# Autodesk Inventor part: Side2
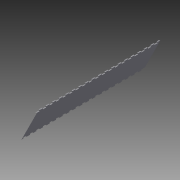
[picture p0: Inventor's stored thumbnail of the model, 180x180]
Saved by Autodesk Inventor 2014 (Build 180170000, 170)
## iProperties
Created: 2014-06
Part Number: Side2
Material: Generic
Document SubType Name: Modeling
Designer: Aser
Density: 1 g/cm^3
Appearance: Default
Author: Aser
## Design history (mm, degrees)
sketch "Sketch1"
  geometry: L1 (-245, -25)-(245, -25); L2 (245, -25)-(245, 25); L3 (245, 25)-(-245, 25); L4 (-245, 25)-(-245, -25); L5 (-245, -25)-(245, 25); L6 (245, -25)-(-245, 25); 1 further point
  constraints: 12 end point, 2 midpoint, 2 parallel, 1 horizontal, 1 perpendicular
  dimensions: "d0" = 490 distance of L2.end L3.end; "d1" = 50 distance of L1.end L2.end
extrude "Extrusion1" new body sketch "Sketch1" distance "d2" = 3; taper "d3" = 0 deg
sketch "Sketch2"
  geometry: L1 (25, 245)-(-25, 245) reference; L2 (-25, -245)-(25, -245) reference; L3 (-22, 242)-(-22, 232) reference; L4 (-22, 232)-(-25, 232) reference; L5 (-25, 242)-(-25, 232) reference; L6 (-22, 242)-(-25, 242) reference; L7 (-22, 222.25)-(-22, 212.25) reference; L8 (-22, 212.25)-(-25, 212.25) reference; L9 (-25, 222.25)-(-25, 212.25) reference; L10 (-22, 222.25)-(-25, 222.25) reference; L11 (-22, 202.5)-(-22, 192.5) reference; L12 (-22, 192.5)-(-25, 192.5) reference; L13 (-25, 202.5)-(-25, 192.5) reference; L14 (-22, 202.5)-(-25, 202.5) reference; L15 (-22, 172.75)-(-22, 182.75) reference; L16 (-22, 172.75)-(-25, 172.75) reference; L17 (-25, 182.75)-(-25, 172.75) reference; L18 (-22, 182.75)-(-25, 182.75) reference; L19 (-22, 163)-(-22, 153) reference; L20 (-22, 153)-(-25, 153) reference; L21 (-25, 163)-(-25, 153) reference; L22 (-22, 163)-(-25, 163) reference; L23 (-22, 133.25)-(-22, 143.25) reference; L24 (-22, 133.25)-(-25, 133.25) reference; L25 (-25, 143.25)-(-25, 133.25) reference; L26 (-22, 143.25)-(-25, 143.25) reference; L27 (-22, 113.5)-(-22, 123.5) reference; L28 (-22, 113.5)-(-25, 113.5) reference; L29 (-25, 123.5)-(-25, 113.5) reference; L30 (-22, 123.5)-(-25, 123.5) reference; L31 (-22, 93.75)-(-22, 103.75) reference; L32 (-22, 93.75)-(-25, 93.75) reference; L33 (-25, 103.75)-(-25, 93.75) reference; L34 (-22, 103.75)-(-25, 103.75) reference; L35 (-22, 84)-(-22, 74) reference; L36 (-22, 74)-(-25, 74) reference; L37 (-25, 84)-(-25, 74) reference; L38 (-22, 84)-(-25, 84) reference; L39 (-22, 64.25)-(-22, 54.25) reference; L40 (-22, 54.25)-(-25, 54.25) reference; L41 (-25, 64.25)-(-25, 54.25) reference; L42 (-22, 64.25)-(-25, 64.25) reference; L43 (-22, 44.5)-(-22, 34.5) reference; L44 (-22, 34.5)-(-25, 34.5) reference; L45 (-25, 44.5)-(-25, 34.5) reference; L46 (-22, 44.5)-(-25, 44.5) reference; L47 (-22, 24.75)-(-22, 14.75) reference; L48 (-22, 14.75)-(-25, 14.75) reference; L49 (-25, 24.75)-(-25, 14.75) reference; L50 (-22, 24.75)-(-25, 24.75) reference; L51 (-22, 5)-(-22, -5) reference; L52 (-22, -5)-(-25, -5) reference; L53 (-25, 5)-(-25, -5) reference; L54 (-22, 5)-(-25, 5) reference; L55 (-22, -14.75)-(-22, -24.75) reference; L56 (-22, -24.75)-(-25, -24.75) reference; L57 (-25, -14.75)-(-25, -24.75) reference; L58 (-22, -14.75)-(-25, -14.75) reference; L59 (-22, -34.5)-(-22, -44.5) reference; L60 (-22, -44.5)-(-25, -44.5) reference; L61 (-25, -34.5)-(-25, -44.5) reference; L62 (-22, -34.5)-(-25, -34.5) reference; L63 (-22, -54.25)-(-22, -64.25) reference; L64 (-22, -64.25)-(-25, -64.25) reference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; 1 further point
  constraints: 100 symmetric about line, 2 end point, 2 midpoint, 3 other
extrude "Extrusion2" cut sketch "Sketch2" distance "d4" = 3; taper "d5" = 0 deg
mirror "Mirror1"
sketch "Sketch3"
  geometry: L1 (22, -5)-(22, 5) reference; L2 (-22, 5)-(-22, -5) reference; L3 (-25, 245)-(25, 245); L4 (25, 245)-(25, 195); L5 (25, 195)-(-25, 195); L6 (-25, 195)-(-25, 245); L7 (-25, 245)-(25, 195); L8 (-25, 195)-(25, 245); L9 (-12.5, 207.5)-(12.5, 207.5); L10 (12.5, 207.5)-(12.5, 232.5); L11 (12.5, 232.5)-(-12.5, 232.5); L12 (-12.5, 232.5)-(-12.5, 207.5); L13 (-12.5, 207.5)-(12.5, 232.5); L14 (12.5, 207.5)-(-12.5, 232.5); L15 (-17.5, 231)-(-7.5, 231); L16 (-7.5, 231)-(-7.5, 234); L17 (-7.5, 234)-(-17.5, 234); L18 (-17.5, 234)-(-17.5, 231); L19 (-17.5, 231)-(-7.5, 234); L20 (-7.5, 231)-(-17.5, 234); L21 (-14, 227.5)-(-11, 227.5); L22 (-11, 227.5)-(-11, 237.5); L23 (-11, 237.5)-(-14, 237.5); L24 (-14, 237.5)-(-14, 227.5); L25 (-14, 227.5)-(-11, 237.5); L26 (-11, 227.5)-(-14, 237.5); L27 (0, 245)-(50, 195); L28 (7.5, 231)-(17.5, 231); L29 (17.5, 231)-(17.5, 234); L30 (17.5, 234)-(7.5, 234); L31 (17.5, 231)-(7.5, 234); L32 (7.5, 231)-(17.5, 234); L33 (7.5, 234)-(7.5, 231); L34 (14, 227.5)-(14, 237.5); L35 (14, 237.5)-(11, 237.5); L36 (11, 237.5)-(11, 227.5); L37 (11, 227.5)-(14, 237.5); L38 (14, 227.5)-(11, 237.5); L39 (11, 227.5)-(14, 227.5); L40 (-25, 220)-(25, 170); L41 (-17.5, 206)-(-7.5, 206); L42 (-7.5, 206)-(-7.5, 209); L43 (-7.5, 209)-(-17.5, 209); L44 (-7.5, 206)-(-17.5, 209); L45 (-17.5, 206)-(-7.5, 209); L46 (-17.5, 209)-(-17.5, 206); L47 (-11, 202.5)-(-11, 212.5); L48 (-11, 212.5)-(-14, 212.5); L49 (-14, 212.5)-(-14, 202.5); L50 (-14, 202.5)-(-11, 212.5); L51 (-11, 202.5)-(-14, 212.5); L52 (-14, 202.5)-(-11, 202.5); L53 (0, 220)-(50, 170); L54 (7.5, 206)-(17.5, 206); L55 (17.5, 206)-(17.5, 209); L56 (17.5, 209)-(7.5, 209); L57 (17.5, 206)-(7.5, 209); L58 (7.5, 206)-(17.5, 209); L59 (7.5, 209)-(7.5, 206); L60 (14, 202.5)-(14, 212.5); L61 (14, 212.5)-(11, 212.5); L62 (11, 212.5)-(11, 202.5); L63 (11, 202.5)-(14, 212.5); L64 (14, 202.5)-(11, 212.5)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; 12 further points
  constraints: 254 end point, 40 midpoint, 16 parallel, 10 horizontal, 8 perpendicular, 2 vertical, 147 other
  dimensions: "d6" = 50 distance of L4.end L5.end; "d7" = 50 distance of L3.end L4.end; "d8" = 25 distance of L11.end L10.end; "d9" = 25 distance of L10.end L9.end; "d10" = 10 distance of L17.end L16.end; "d11" = 3 distance of L16.end L15.end; "d12" = 3 distance of L23.end L22.end; "d13" = 10 distance of L22.end L21.end; "d16" = 25 distance of L3.start L27.start; "d19" = 25 distance of L3.start L40.start; "d22" = 50 distance of L69.end L68.end; "d23" = 50 distance of L68.end L67.end; "d24" = 25 distance of L75.end L74.end; "d25" = 25 distance of L74.end L73.end; "d26" = 10 distance of L81.end L80.end; "d27" = 3 distance of L80.end L79.end; "d28" = 3 distance of L87.end L86.end; "d29" = 10 distance of L86.end L85.end; "d32" = 25 distance of L69.end L91.start; "d35" = 25 distance of L69.end L104.start
extrude "Extrusion3" cut sketch "Sketch3" distance "d38" = 3; taper "d39" = 0 deg
sketch "Sketch4"
  geometry: L1 (25, 245)-(-25, 245) reference; L2 (15, 242)-(15, 245) reference; L3 (25, 245)-(15, 245) reference; L4 (25, 242)-(25, 245) reference; L5 (25, 242)-(15, 242) reference; L6 (5, 245)-(5, 242) reference; L7 (5, 242)-(-5, 242) reference; L8 (-5, 242)-(-5, 245) reference; L9 (5, 245)-(-5, 245) reference; L10 (-15, 245)-(-15, 242) reference; L11 (-15, 242)-(-25, 242) reference; L12 (-25, 242)-(-25, 245) reference; L13 (-15, 245)-(-25, 245) reference; 1 further point
extrude "Extrusion4" cut sketch "Sketch4" distance "d40" = 3; taper "d41" = 0 deg
mirror "Mirror2"
body "Solid1"
node "Reference1"
node "Reference2"
node "Reference3"
node "Reference4"
node "Reference5"
node "Reference6"
node "Reference7"
node "Reference8"
node "Reference9"
node "Reference10"
node "Reference11"
node "Reference12"
node "Reference13"
node "Reference14"
node "Reference15"
node "Reference16"
node "Reference17"
node "Reference18"
node "Reference19"
node "Reference20"
node "Reference21"
node "Reference22"
node "Reference23"
node "Reference24"
node "Reference25"
node "Reference26"
node "Reference27"
node "Reference28"
